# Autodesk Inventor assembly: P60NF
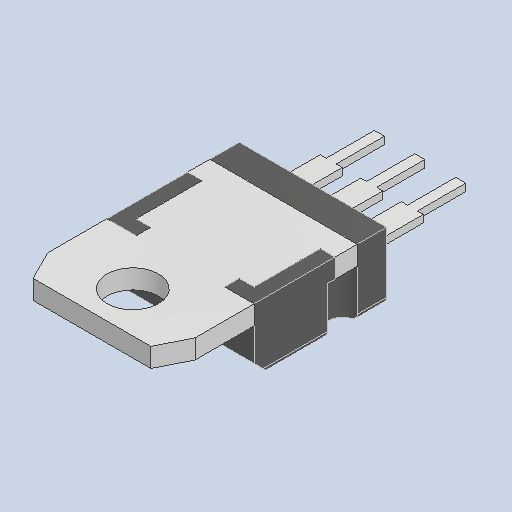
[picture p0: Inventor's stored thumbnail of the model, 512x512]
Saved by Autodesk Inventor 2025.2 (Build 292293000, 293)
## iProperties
Created: 2025-04
Part Number: P60NF
Description: PART--DESC
Document SubType Name: Assembly
Designer: BennF
Author: BennF
Revision Number: NONE
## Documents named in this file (4)
- C:\Users\BennF\Nextcloud\Benutzer\CNC JarBeRi\existing parts\Electronics\RepRap A4988 Shied (USE WITHOUT ARDUINO)\reprap-a4988-1.snapshot.1\RepRap\RepRap\P60NF_1.iam
- C:\Users\BennF\Nextcloud\Benutzer\CNC JarBeRi\existing parts\Electronics\RepRap A4988 Shied (USE WITHOUT ARDUINO)\reprap-a4988-1.snapshot.1\RepRap\RepRap\P60NF Geometry.ipt
- C:\Users\BennF\Nextcloud\Benutzer\CNC JarBeRi\existing parts\Electronics\RepRap A4988 Shied (USE WITHOUT ARDUINO)\reprap-a4988-1.snapshot.1\RepRap\RepRap\body.ipt
- C:\Users\BennF\Nextcloud\Benutzer\CNC JarBeRi\existing parts\Electronics\RepRap A4988 Shied (USE WITHOUT ARDUINO)\reprap-a4988-1.snapshot.1\RepRap\RepRap\Name.ipt
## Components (3 placed, 3 different names)
1. P60NF Geometry
2. body
3. Name
